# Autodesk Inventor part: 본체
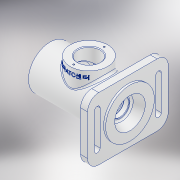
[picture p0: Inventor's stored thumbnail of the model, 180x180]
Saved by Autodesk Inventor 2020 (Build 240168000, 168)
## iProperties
Created: 2021-07
Part Number: 본체
Material: 알루미늄 6061
Document SubType Name: Modeling
Designer: MIRAE
Density: 2.7 g/cm^3
Appearance: 알루미늄 - 평지
Mass: 738.107 g
Surface Area: 646.636 cm^2
Volume: 273.373 cm^3
Author: MIRAE
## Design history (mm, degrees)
sketch "스케치1"
  geometry: L1 (-57.5, 0)-(57.5, 0); L2 (-57.5, 31)-(57.5, 31); L3 (57.5, 31)-(57.5, 22); L4 (57.5, 22)-(43.5, 16); L5 (43.5, 16)-(43.5, 12.904); L6 (43.5, 12.904)-(42.8, 12.5); L7 (42.8, 12.5)-(36.2, 12.5); L8 (36.2, 12.5)-(36.2, 10); L9 (36.2, 10)-(33.5, 10); L10 (33.5, 10)-(33.5, 16); L11 (33.5, 16)-(28.5, 16); L12 (28.5, 16)-(28.5, 17.5); L13 (28.5, 17.5)-(17.5, 17.5); L14 (17.5, 17.5)-(17.5, 26); L15 (17.5, 26)-(-20.5, 26); L16 (-20.5, 26)-(-20.5, 17.5); L17 (-20.5, 17.5)-(-31.5, 17.5); L18 (-31.5, 17.5)-(-31.5, 18.5); L19 (-31.5, 18.5)-(-33.25, 18.5); L20 (-33.25, 18.5)-(-33.25, 17.5); L21 (-33.25, 17.5)-(-36.5, 17.5); L22 (-36.5, 17.5)-(-36.5, 20); L23 (-36.5, 20)-(-45.5, 20); L24 (-45.5, 20)-(-45.5, 24); L25 (-45.5, 24)-(-48.5, 24); L26 (-48.5, 24)-(-48.5, 0); L27 (-57.5, 0)-(-57.5, 31); L28 (42.8, 12.5)-(57.5, 12.5); 2 further points
  constraints: 56 end point, 20 perpendicular, 5 point on line, 3 horizontal, 1 coincident, 1 midpoint, 1 parallel, 1 vertical alignment
  dimensions: "d0" = 115 distance of L1.start L1.end; "d2" = 62 diameter of L2 L1; "d3" = 3 distance of L24.end L25.end; "d5" = 9 distance of L22.end L23.end; "d6" = 1.75 distance of L18.end L19.end; "d7" = 37 diameter of L19 L1; "d8" = 35 diameter of L21 L1; "d9" = 40 diameter of L23 L1; "d10" = 48 diameter of L25 L1; "d11" = 9 distance between parallel lines of L27 L26; "d12" = 52 diameter of L15 L1; "d13" = 32 diameter of L11 L1; "d14" = 20 diameter of L9 L1; "d15" = 44 diameter of L3.end L1; "d16" = 115 distance of L2.start L2.end; "d17" = 25 diameter of L7 L1; "d18" = 30 deg angle of L28 L6; "d19" = 0.7 horizontal distance of L5.end L6.end; "d20" = 7.3 horizontal distance of L5.end L7.end; "d21" = 32 diameter of L4.end L1; "d22" = 14 horizontal distance of L3.end L4.end; "d23" = 38 distance of L14.end L15.end; "d24" = 3.25 distance of L20.end L21.end; "d25" = 11 distance of L16.end L17.end; "d26" = 11 distance of L12.end L13.end; "d27" = 5 distance of L10.end L11.end
revolve "회전1" sketch "스케치1" stored, may be unused: angle "d28" = 90 deg
sketch "스케치2"
  geometry: C1 r 31 at (0, 0) reference; 2 further points
  constraints: 1 coincident
hole "구멍1" sketch "스케치2" at (0, 0) diameter "d29" = 40.3762; stored, may be unused: countersink angle "d33" = 90 deg, drill point angle "d35" = 0 deg; dims "d30" = 84, "d31" = 4, "d32" = 2, "d34" = 9
node "작업 평면1"
sketch "스케치3"
  geometry: L1 (57.5, 31)-(57.5, -31) reference; C1 r 27 at (1.5, 0); 1 further point
  constraints: 1 centre point, 1 horizontal alignment
  dimensions: "d37" = 54 diameter of C1; "d38" = 56 distance from line of C1.centre L1
extrude "돌출1" join sketch "스케치3" stored distance "d39" = 10; taper "d40" = 0 deg
sketch "스케치4"
  geometry: C1 r 27 at (0, 0) reference; 2 further points
  constraints: 1 coincident
hole "구멍2" sketch "스케치4" at (0, 0) diameter "d41" = 32; stored, may be unused: countersink angle "d45" = 90 deg, drill point angle "d47" = 0 deg; dims "d42" = 84, "d43" = 4, "d44" = 2, "d46" = 22
sketch "스케치5"
  geometry: L1 (-58, 45)-(58, 45); L2 (58, 45)-(58, -45); L3 (58, -45)-(-58, -45); L4 (-58, -45)-(-58, 45); C1 r 31 at (0, 0) reference; 1 further point
  constraints: 8 end point, 2 parallel, 1 horizontal, 1 perpendicular
  dimensions: "d48" = 116 distance of L2.end L3.end; "d49" = 90 distance of L1.end L2.end; "d50" = 45 distance from line of point (0, 0) L3; "d51" = 58 distance from line of point (0, 0) L4
extrude "돌출2" join sketch "스케치5" distance "d52" = 13; taper "d53" = 0 deg
sketch "스케치6"
  geometry: L1 (116, 90)-(0, 90) reference; L2 (116, 90)-(0, 90) reference; L3 (0, 90)-(0, 0) reference; L4 (0, 0)-(116, 0) reference; L5 (116, 0)-(116, 90) reference; C1 r 12.5 at (58, 45) reference; C2 r 35 at (58, 45); C3 r 22 at (58, 45) reference; 3 further points
  constraints: 1 centre point, 1 coincident
  dimensions: "d54" = 70 diameter of C2
extrude "돌출3" cut sketch "스케치6" distance "d55" = 3; taper "d56" = 0 deg
fillet "모깎기1" dims "d57" = 16
sketch "스케치7"
  geometry: L1 (14, 70)-(14, 20); L2 (10, 70)-(10, 20); L3 (18, 20)-(18, 70); A1 r 4 centre (14, 70) between (18, 70) and (10, 70); A2 r 4 centre (14, 20) between (10, 20) and (18, 20); 2 further points
  constraints: 8 end point, 4 point on circle, 4 tangent, 2 centre point, 1 horizontal alignment, 1 midpoint, 1 parallel, 1 vertical
  dimensions: "d58" = 50 distance of L1.start L1.end; "d59" = 8 diameter of A2; "d60" = 44 horizontal distance of L1.start point (58, 45)
extrude "돌출4" cut sketch "스케치7" extent not by distance; stored distance "d61" = 0; taper "d62" = 0 deg
sketch "스케치8" dims "d63" = 44
  geometry: L1 (-56, -31)-(-56, 31) reference; 3 further points
  constraints: 2 vertical alignment, 1 horizontal alignment, 2 other
  dimensions: "d64" = 56 distance from line of point (0, 0) L1
hole "구멍3" sketch "스케치8" at (0, 22) diameter "d65" = 2.459; stored, may be unused: countersink angle "d69" = 90 deg, drill point angle "d71" = 120 deg; dims "d66" = 6, "d67" = 4, "d68" = 2, "d70" = 8
node "작업 평면2"
sketch "스케치9"
  geometry: L1 (25.5, 42)-(-28.5, 42) reference; 3 further points
  constraints: 1 midpoint, 1 vertical alignment, 1 other
  dimensions: "d76" = 8 distance from line of point (-1.5, 34) L1
feature "엠보싱1" sketch "스케치9" dims "d5" = 9, "d77" = 0.5, "d78" = 0
fillet "모깎기2" dims "d79" = 0.3
fillet "모깎기3" dims "d80" = 3
fillet "모깎기4" dims "d81" = 3
chamfer "모따기1" distance "d82" = 1; stored, may be unused: second distance "d83" = 2, angle "d84" = 45 deg
chamfer "모따기2" distance "d85" = 1; stored, may be unused: second distance "d86" = 2, angle "d87" = 45 deg
fillet "모깎기5" dims "d88" = 3
node "솔리드1"
mirror "미러1"
pattern_circular "원형 패턴1" dims angle "d73" = 360 deg
node "투영된 루프1"
feature "A9D066F2-1C7D-4E18-AEED-F7BC21143FA4" dims "d41" = 32, "d42" = 84, "d43" = 4, "d44" = 2, "d45" = 90 deg, "d46" = 22, "d47" = 0
other parameters: "d36" = 42, "d75" = 27.5
